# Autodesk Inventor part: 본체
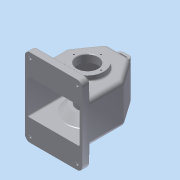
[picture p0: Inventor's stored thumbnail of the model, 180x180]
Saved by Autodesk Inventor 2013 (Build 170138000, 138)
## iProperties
Created: 2016-12
Part Number: 본체
Material: 알루미늄 6061
Document SubType Name: Modeling
Designer: narae
Density: 2.71 g/cm^3
Mass: 1085.87 g
Surface Area: 1149.47 cm^2
Volume: 400.689 cm^3
Author: narae
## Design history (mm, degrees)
sketch "스케치1"
  geometry: L1 (0, 0)-(55, 0); L2 (55, 0)-(55, 76.847); L3 (53.192, 82.583)-(26.477, 120.736); L4 (18.285, 125)-(0, 125); L5 (0, 125)-(0, 0); L6 (55, 0)-(0, 0); L7 (0, 0)-(0, 15); L8 (0, 15)-(55, 15); L9 (55, 15)-(55, 0); C1 r 20 at (0, 65); A1 r 10 centre (18.285, 115) between (26.477, 120.736) and (18.285, 125); A2 r 10 centre (45, 76.847) between (55, 76.847) and (53.192, 82.583); 2 further points
  constraints: 18 end point, 5 point on line, 4 parallel, 4 point on circle, 4 tangent, 3 centre point, 2 horizontal, 2 perpendicular, 1 equal radius
  dimensions: "d0" = 80 distance of L1.end point (55, 80); "d1" = 125 distance between parallel lines of L1 L4; "d2" = 35 deg angle of L2 L3; "d4" = 40 diameter of C1; "d5" = 65 distance from line of L1 C1.centre; "d6" = 15 distance between parallel lines of L1 L8; "d7" = 110 diameter of L2 L5; "d10" = 10 radius of A1
extrude "돌출1" new body sketch "스케치1" stored distance "d8" = 77; taper "d9" = 0 deg
feature "쉘1" dims "d11" = 5
extrude "돌출2" cut sketch "스케치1" stored distance "d12" = 77; taper "d13" = 0 deg
sketch "스케치2"
  geometry: L1 (45, 38.5)-(45, 33.5) reference; L2 (45, 33.5)-(0, 33.5) reference; L3 (0, 33.5)-(0, 38.5) reference; L4 (0, 38.5)-(45, 38.5) reference; L5 (45, -33.5)-(45, -38.5) reference; L6 (45, -38.5)-(0, -38.5) reference; L7 (0, -38.5)-(0, -33.5) reference; L8 (0, -33.5)-(45, -33.5) reference; L9 (85, -38.5)-(85, -33.5) reference; L10 (85, -33.5)-(120, -33.5) reference; L11 (120, -33.5)-(120, 33.5) reference; L12 (120, 33.5)-(85, 33.5) reference; L13 (85, 33.5)-(85, 38.5) reference; L14 (85, 38.5)-(125, 38.5) reference; L15 (125, 38.5)-(125, -38.5) reference; L16 (125, -38.5)-(85, -38.5) reference; L17 (85, 38.5)-(85, 48.5); L18 (45, 38.5)-(85, 38.5) reference; L19 (85, 48.5)-(96, 48.5); L20 (96, 48.5)-(96, 38.5); L21 (85, -38.5)-(85, -42.5); L22 (85, -38.5)-(85, -33.5) reference; L23 (106, -33.5)-(92, -19.5); L24 (92, -19.5)-(85, -19.5); L25 (85, -19.5)-(85, -33.5); L26 (86, -43.5)-(102.5, -43.5); L27 (102.5, -43.5)-(102.5, -38.5); L28 (85, -38.5)-(45, -38.5) reference; L29 (65, -38.5)-(65, 38.5); L30 (102.5, -38.5)-(102.5, -33.5); L31 (106, -33.5)-(102.5, -33.5); L32 (86, -43.5)-(85, -42.5); 2 further points
  constraints: 26 end point, 5 perpendicular, 5 point on line, 3 midpoint, 2 collinear, 1 parallel
  dimensions: "d14" = 45 deg angle of L24 L23; "d15" = 5 distance between parallel lines of L16 L26; "d16" = 24 distance between parallel lines of L24 L26; "d17" = 54 diameter of L23.end L29; "d18" = 75 diameter of L27 L29; "d19" = 62 diameter of L20 L29; "d20" = 15 distance between parallel lines of L19 L12; "d21" = 1 distance of L26.start point (85, -43.5); "d22" = 1 distance of L21.end point (85, -43.5) (= d21)
revolve "회전1" sketch "스케치2" stored, may be unused: angle "d23" = 90 deg
sketch "스케치3"
  geometry: L1 (0, 77)-(0, 0) reference; L2 (0, 77)-(-110, 77) reference; L3 (-110, 77)-(-110, 0) reference; L4 (0, 0)-(-110, 0) reference; L5 (-10, -36.5)-(-100, -36.5); L6 (-110, -26.5)-(-110, 103.5); L7 (-100, 113.5)-(-10, 113.5); L8 (0, 103.5)-(0, -26.5); L9 (0, -36.5)-(-110, 113.5); L10 (-110, -36.5)-(0, 113.5); A1 r 10 centre (-100, 103.5) between (-100, 113.5) and (-110, 103.5); A2 r 10 centre (-10, 103.5) between (0, 103.5) and (-10, 113.5); A3 r 10 centre (-10, -26.5) between (-10, -36.5) and (0, -26.5); A4 r 10 centre (-100, -26.5) between (-110, -26.5) and (-100, -36.5); 1 further point
  constraints: 12 end point, 8 point on circle, 8 point on line, 8 tangent, 4 centre point, 3 equal radius, 2 midpoint, 2 parallel, 1 horizontal, 1 perpendicular
  dimensions: "d24" = 110 distance of L9.end L10.end; "d25" = 150 distance of L10.start L9.end; "d26" = 10 radius of A1
extrude "돌출3" join sketch "스케치3" distance "d27" = 15; taper "d28" = 0 deg
hole "구멍1" diameter "d31" = 5; stored, may be unused: countersink angle "d35" = 90 deg, drill point angle "d37" = 118 deg; dims "d29" = 10, "d30" = 10, "d32" = 6, "d33" = 12, "d34" = 5, "d36" = 8
hole "구멍2" diameter "d40" = 5; stored, may be unused: countersink angle "d44" = 90 deg, drill point angle "d46" = 118 deg; dims "d38" = 10, "d39" = 10, "d41" = 6, "d42" = 12, "d43" = 5, "d45" = 8
hole "구멍3" diameter "d49" = 5; stored, may be unused: countersink angle "d53" = 90 deg, drill point angle "d55" = 118 deg; dims "d47" = 10, "d48" = 10, "d50" = 6, "d51" = 12, "d52" = 5, "d54" = 8
hole "구멍4" diameter "d58" = 5; stored, may be unused: countersink angle "d62" = 90 deg, drill point angle "d64" = 118 deg; dims "d56" = 10, "d57" = 10, "d59" = 6, "d60" = 12, "d61" = 5, "d63" = 8
sketch "스케치4"
  geometry: L1 (-55, -50)-(55, -50) reference; L2 (55, -50)-(55, -65) reference; L3 (55, -65)-(-55, -65) reference; L4 (-55, -65)-(-55, -50) reference; C1 r 31 at (0, 0) reference; C2 r 31 at (0, 0) reference; C3 r 20 at (0, 0) reference; C4 r 37.5 at (0, 0) reference; A1 r 26 centre (0, 0) between (0, 26) and (-26, 0); 3 further points
  constraints: 4 point on circle, 2 horizontal alignment, 2 vertical alignment, 1 centre point, 1 coincident
  dimensions: "d65" = 52 diameter of A1
hole "구멍5" sketch "스케치4" at (0, 26), (-26, 0), (26, 0), (0, -26) diameter "d66" = 2.459; stored, may be unused: countersink angle "d70" = 90 deg, drill point angle "d72" = 120 deg; dims "d67" = 6, "d68" = 4, "d69" = 2, "d71" = 8
sketch "스케치5"
  geometry: C1 r 21 at (0, 0) reference; C2 r 37.5 at (0, 0) reference; A1 r 29 centre (0, 0) between (0, 29) and (-29, 0); 3 further points
  constraints: 4 point on circle, 2 horizontal alignment, 2 vertical alignment, 1 centre point, 1 coincident
  dimensions: "d73" = 58 diameter of A1
hole "구멍6" sketch "스케치5" at (0, 29), (-29, 0), (29, 0), (0, -29) diameter "d74" = 2.459; stored, may be unused: countersink angle "d78" = 90 deg, drill point angle "d80" = 120 deg; dims "d75" = 6, "d76" = 4, "d77" = 2, "d79" = 8
node "작업 평면1"
sketch "스케치6"
  geometry: L1 (-18.285, 125)-(18.285, 125) reference; L2 (26.477, 120.736)-(53.192, 82.583) reference; L3 (55, 76.847)-(55, 0) reference; L4 (55, 0)-(50, 0) reference; L5 (50, 0)-(50, 76.847) reference; L6 (49.096, 79.715)-(22.381, 117.868) reference; L7 (18.285, 120)-(-18.285, 120) reference; L8 (-22.381, 117.868)-(-49.096, 79.715) reference; L9 (-50, 76.847)-(-50, 0) reference; L10 (-50, 0)-(-55, 0) reference; L11 (-55, 0)-(-55, 76.847) reference; L12 (-53.192, 82.583)-(-26.477, 120.736) reference; L13 (18.285, 125)-(-18.285, 125) reference; L14 (-12.5, 125)-(-12.5, 132); L15 (-4.5, 140)-(4.5, 140); L16 (12.5, 132)-(12.5, 125); L17 (50, 0)-(-50, 0) reference; L18 (7.5, 125)-(7.5, 132); L19 (4.5, 135)-(-4.5, 135); L20 (-7.5, 132)-(-7.5, 125); L21 (-12.5, 125)-(-7.5, 125); L22 (7.5, 125)-(12.5, 125); A1 r 10 centre (-18.285, 115) between (-18.285, 125) and (-26.477, 120.736) reference; A2 r 10 centre (18.285, 115) between (26.477, 120.736) and (18.285, 125) reference; A3 r 10 centre (45, 76.847) between (55, 76.847) and (53.192, 82.583) reference; A4 r 5 centre (45, 76.847) between (50, 76.847) and (49.096, 79.715) reference; A5 r 5 centre (18.285, 115) between (22.381, 117.868) and (18.285, 120) reference; A6 r 5 centre (-18.285, 115) between (-18.285, 120) and (-22.381, 117.868) reference; A7 r 5 centre (-45, 76.847) between (-49.096, 79.715) and (-50, 76.847) reference; A8 r 10 centre (-45, 76.847) between (-53.192, 82.583) and (-55, 76.847) reference; A9 r 8 centre (4.5, 132) between (12.5, 132) and (4.5, 140); A10 r 8 centre (-4.5, 132) between (-4.5, 140) and (-12.5, 132); A11 r 3 centre (4.5, 132) between (7.5, 132) and (4.5, 135); A12 r 3 centre (-4.5, 132) between (-4.5, 135) and (-7.5, 132); 3 further points
  constraints: 16 end point, 8 point on circle, 4 centre point, 4 tangent, 3 perpendicular, 2 collinear, 2 midpoint, 2 parallel, 2 point on line, 1 equal radius, 1 vertical alignment, 4 other
  dimensions: "d82" = 140 distance between parallel lines of L17 L15; "d83" = 25 distance between parallel lines of L16 L14; "d84" = 8 radius of A9; "d85" = 5 distance between parallel lines of L19 L15
extrude "돌출4" join sketch "스케치6" stored distance "d86" = 8; taper "d87" = 0 deg
node "작업 평면2"
sketch "스케치7"
  geometry: L1 (-18.285, 125)-(18.285, 125) reference; L2 (26.477, 120.736)-(53.192, 82.583) reference; L3 (55, 76.847)-(55, 0) reference; L4 (55, 0)-(50, 0) reference; L5 (50, 0)-(50, 76.847) reference; L6 (49.096, 79.715)-(22.381, 117.868) reference; L7 (18.285, 120)-(-18.285, 120) reference; L8 (-22.381, 117.868)-(-49.096, 79.715) reference; L9 (-50, 76.847)-(-50, 0) reference; L10 (-50, 0)-(-55, 0) reference; L11 (-55, 0)-(-55, 76.847) reference; L12 (-53.192, 82.583)-(-26.477, 120.736) reference; L13 (18.285, 125)-(-18.285, 125) reference; L14 (-12.5, 125)-(-12.5, 132); L15 (-4.5, 140)-(4.5, 140); L16 (12.5, 132)-(12.5, 125); L17 (50, 0)-(-50, 0) reference; L18 (7.5, 125)-(7.5, 132); L19 (4.5, 135)-(-4.5, 135); L20 (-7.5, 132)-(-7.5, 125); L21 (-12.5, 125)-(-7.5, 125); L22 (7.5, 125)-(12.5, 125); C1 r 29.5 at (0, 65) reference; C2 r 20 at (0, 65) reference; A1 r 10 centre (-18.285, 115) between (-18.285, 125) and (-26.477, 120.736) reference; A2 r 10 centre (18.285, 115) between (26.477, 120.736) and (18.285, 125) reference; A3 r 10 centre (45, 76.847) between (55, 76.847) and (53.192, 82.583) reference; A4 r 5 centre (45, 76.847) between (50, 76.847) and (49.096, 79.715) reference; A5 r 5 centre (18.285, 115) between (22.381, 117.868) and (18.285, 120) reference; A6 r 5 centre (-18.285, 115) between (-18.285, 120) and (-22.381, 117.868) reference; A7 r 5 centre (-45, 76.847) between (-49.096, 79.715) and (-50, 76.847) reference; A8 r 10 centre (-45, 76.847) between (-53.192, 82.583) and (-55, 76.847) reference; A9 r 8 centre (-4.5, 132) between (-4.5, 140) and (-12.5, 132); A10 r 8 centre (4.5, 132) between (12.5, 132) and (4.5, 140); A11 r 3 centre (4.5, 132) between (7.5, 132) and (4.5, 135); A12 r 3 centre (-4.5, 132) between (-4.5, 135) and (-7.5, 132); 5 further points
  constraints: 16 end point, 8 point on circle, 4 centre point, 4 midpoint, 4 perpendicular, 4 tangent, 2 collinear, 2 point on line, 2 vertical alignment, 1 equal radius, 4 other
  dimensions: "d92" = 25 distance between parallel lines of L16 L14; "d94" = 140 distance between parallel lines of L17 L15; "d95" = 8 radius of A9; "d96" = 5 distance between parallel lines of L19 L15
extrude "돌출5" join sketch "스케치7" stored distance "d97" = 8; taper "d98" = 0 deg
chamfer "모따기3" distance "d107" = 1; stored, may be unused: second distance "d108" = 2, angle "d109" = 45 deg
fillet "모깎기2" dims "d104" = 1, "d105" = 3
sketch "스케치9"
  geometry: L1 (26.5, 12)-(26.5, 76.847) reference; 3 further points
  constraints: 1 other
  dimensions: "d114" = 45 distance of point (65, 0) point (65, 45); "d119" = 38.5 distance from line of L1 point (65, 45)
feature "엠보싱2" sketch "스케치9" dims "d116" = 0.5, "d117" = 0
fillet "모깎기4" dims "d118" = 3, "d120" = 8, "d121" = 1
node "솔리드1"
mirror "대칭1"
node "절단 모서리 투영1"
node "절단 모서리 투영2"
node "절단 모서리 투영3"
node "절단 모서리 투영4"
other parameters: "d81" = 22, "d91" = -22
